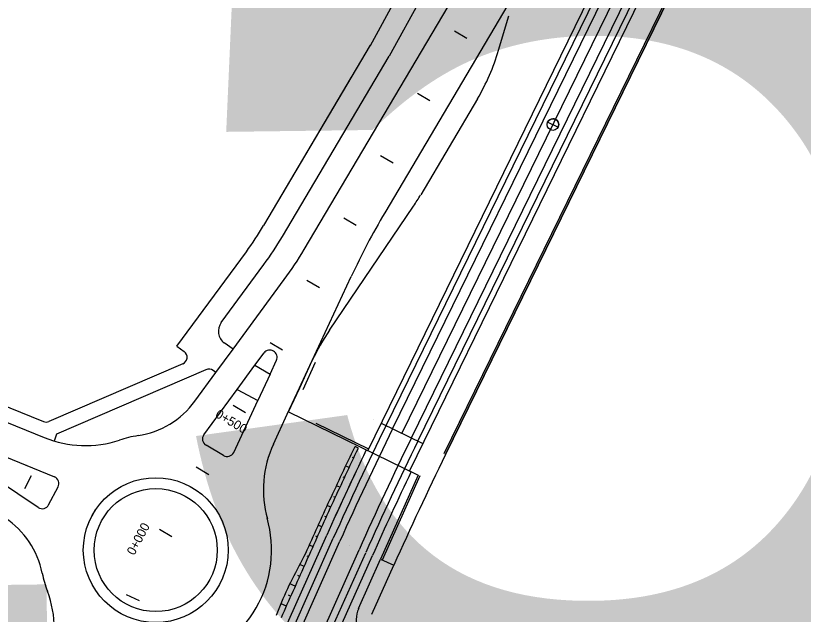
# Model space of a CAD drawing. Extents: x 6503541 to 6503743, y 5888004 to 5888145.
# Drawn here: x 6503689.662 to 6503692.272, y 5888095.259 to 5888097.244 of the extents above; entities that cross this region are included whole.
import ezdxf

# ---------------------------------------------------------------- set-up
doc = ezdxf.new("R2010")
doc.units = 0
doc.layers.add('12', color=7, linetype='Continuous')

msp = doc.modelspace()

# ---------------------------------------------------------------- linework, layer by layer
at = {"layer": '12'}
for p, q in [((6503691.4764, 5888098.3138), (6503690.8366, 5888097.1441)), ((6503691.1973, 5888097.6501), (6503690.8997, 5888097.1094)), ((6503691.6944, 5888097.5731), (6503690.8292, 5888095.8023)), ((6503690.8895, 5888095.8848), (6503691.7106, 5888097.5652)), ((6503690.9111, 5888095.8743), (6503691.7322, 5888097.5546)), ((6503690.9424, 5888095.859), (6503691.7634, 5888097.5394)), ((6503690.9736, 5888095.8437), (6503691.7947, 5888097.5241)), ((6503691.8324, 5888097.5056), (6503690.9672, 5888095.7348)), ((6503690.9952, 5888095.8332), (6503691.8163, 5888097.5135)), ((6503691.8999, 5888097.466), (6503691.0815, 5888095.791)), ((6503691.9079, 5888097.4688), (6503691.0868, 5888095.7884)), ((6503691.0868, 5888095.7884), (6503691.9079, 5888097.4688)), ((6503691.3672, 5888097.4049), (6503690.8855, 5888096.5904)), ((6503690.6183, 5888096.4687), (6503691.1416, 5888097.3535)), ((6503691.2627, 5888097.1291), (6503691.2968, 5888097.2437)), ((6503691.2627, 5888097.1291), (6503691.2968, 5888097.2437)), ((6503690.4841, 5888096.5481), (6503690.8377, 5888097.1461)), ((6503690.546, 5888096.5114), (6503690.8997, 5888097.1094)), ((6503690.4841, 5888096.5481), (6503690.7747, 5888097.0396)), ((6503691.1923, 5888096.9678), (6503691.0044, 5888096.6499)), ((6503691.1923, 5888096.9678), (6503691.0044, 5888096.6499)), ((6503690.7021, 5888096.2012), (6503690.9807, 5888096.6127)), ((6503690.7021, 5888096.2012), (6503690.9807, 5888096.6127)), ((6503690.1965, 5888096.1481), (6503690.4267, 5888096.4613)), ((6503690.3433, 5888096.2261), (6503690.4847, 5888096.4187)), ((6503690.6451, 5888096.1005), (6503690.7742, 5888096.3787)), ((6503690.3826, 5888096.1379), (6503690.5524, 5888096.3689)), ((6503690.1965, 5888096.1481), (6503690.2206, 5888096.1304)), ((6503690.3258, 5888096.0605), (6503690.3826, 5888096.1379)), ((6503690.4552, 5888096.0846), (6503690.4852, 5888096.1255)), ((6503690.2158, 5888096.089), (6503689.7725, 5888095.8983)), ((6503690.5052, 5888096.0555), (6503690.5263, 5888096.1012)), ((6503690.6037, 5888096.0098), (6503690.6451, 5888096.1005)), ((6503690.6089, 5888096.0225), (6503690.6451, 5888096.1005)), ((6503690.6147, 5888096.0048), (6503690.656, 5888096.0955)), ((6503690.2929, 5888096.07), (6503689.7971, 5888095.8567)), ((6503690.256, 5888095.9655), (6503690.3258, 5888096.0605)), ((6503690.3965, 5888096.0048), (6503690.4552, 5888096.0846)), ((6503690.4552, 5888096.0846), (6503690.5052, 5888096.0555)), ((6503690.5052, 5888096.0555), (6503690.4648, 5888095.9685)), ((6503689.4715, 5888096.0134), (6503689.7539, 5888095.8982)), ((6503690.5625, 5888095.9226), (6503690.6031, 5888096.0101)), ((6503690.5669, 5888095.9304), (6503690.6037, 5888096.0098)), ((6503690.6031, 5888096.0101), (6503690.6089, 5888096.0225)), ((6503690.6031, 5888096.0101), (6503690.6089, 5888096.0225)), ((6503690.286, 5888095.8543), (6503690.3965, 5888096.0048)), ((6503690.3965, 5888096.0048), (6503690.4648, 5888095.9685)), ((6503689.4533, 5888095.969), (6503689.7571, 5888095.845)), ((6503690.3847, 5888095.7959), (6503690.4648, 5888095.9685)), ((6503690.5669, 5888095.9304), (6503690.9964, 5888095.7206)), ((6503690.5165, 5888095.8234), (6503690.5625, 5888095.9226)), ((6503690.8475, 5888095.9054), (6503690.8475, 5888095.9054)), ((6503690.6566, 5888095.8933), (6503690.8318, 5888095.8077)), ((6503690.8734, 5888095.8927), (6503691.0114, 5888095.8253)), ((6503689.7971, 5888095.8567), (6503689.7902, 5888095.8334)), ((6503689.4791, 5888095.8418), (6503689.7906, 5888095.7147)), ((6503689.7369, 5888095.6133), (6503689.4568, 5888095.7996)), ((6503690.3507, 5888095.7854), (6503690.2931, 5888095.8195)), ((6503690.7981, 5888095.8104), (6503690.7871, 5888095.8156)), ((6503690.7771, 5888095.7805), (6503690.7827, 5888095.7779)), ((6503690.7673, 5888095.7453), (6503690.756, 5888095.7506)), ((6503690.9672, 5888095.7348), (6503690.9964, 5888095.7206)), ((6503690.7463, 5888095.7154), (6503690.752, 5888095.7127)), ((6503690.9964, 5888095.7206), (6503690.8716, 5888095.4414)), ((6503691.0019, 5888095.7181), (6503690.8771, 5888095.439)), ((6503689.7714, 5888095.6221), (6503689.8028, 5888095.6812)), ((6503690.7369, 5888095.6801), (6503690.7253, 5888095.6854)), ((6503690.7159, 5888095.6501), (6503690.7218, 5888095.6474)), ((6503690.7068, 5888095.6146), (6503690.695, 5888095.62)), ((6503690.686, 5888095.5846), (6503690.6919, 5888095.5819)), ((6503690.6771, 5888095.549), (6503690.6652, 5888095.5544)), ((6503689.741, 5888093.3912), (6503690.693, 5888095.5212)), ((6503690.6564, 5888095.5189), (6503690.6624, 5888095.5162)), ((6503688.2552, 5888090.0082), (6503690.7149, 5888095.5114)), ((6503688.2771, 5888089.9984), (6503690.7368, 5888095.5016)), ((6503690.6477, 5888095.4833), (6503690.6357, 5888095.4887)), ((6503688.3407, 5888089.97), (6503690.8004, 5888095.4732)), ((6503688.3626, 5888089.9602), (6503690.8223, 5888095.4634)), ((6503689.8183, 5888093.1583), (6503690.8442, 5888095.4537)), ((6503690.6268, 5888095.4532), (6503690.633, 5888095.4505)), ((6503690.7989, 5888095.2788), (6503690.8716, 5888095.4414)), ((6503690.8716, 5888095.4414), (6503690.9154, 5888095.4218)), ((6503690.6183, 5888095.4176), (6503690.6042, 5888095.4239)), ((6503690.8427, 5888095.2592), (6503690.9154, 5888095.4218)), ((6503690.5957, 5888095.3883), (6503690.6036, 5888095.3847)), ((6503690.5889, 5888095.3519), (6503690.5713, 5888095.3597)), ((6503690.5651, 5888095.3231), (6503690.5743, 5888095.319)), ((6503690.5596, 5888095.2861), (6503690.5417, 5888095.2941))]:
    msp.add_line(p, q, dxfattribs=at)
for points in [[(6503691.1574, 5888097.1681), (6503691.1161, 5888097.1925)], [(6503691.0353, 5888096.9615), (6503690.9939, 5888096.9859)], [(6503691.4254, 5888096.8913), (6503691.4599, 5888096.8745)], [(6503690.9131, 5888096.7549), (6503690.8718, 5888096.7794)], [(6503690.7909, 5888096.5483), (6503690.7496, 5888096.5728)], [(6503690.6688, 5888096.3418), (6503690.6274, 5888096.3662)], [(6503690.3826, 5888096.1379), (6503690.3537, 5888096.1589)], [(6503690.5466, 5888096.1352), (6503690.5053, 5888096.1596)], [(6503690.3258, 5888096.0605), (6503690.3166, 5888096.0672)], [(6503690.3831, 5888095.953), (6503690.4244, 5888095.9286)], [(6503690.5267, 5888095.2558), (6503690.5311, 5888095.267), (6503690.5354, 5888095.2782), (6503690.5398, 5888095.2894), (6503690.5442, 5888095.3005), (6503690.5491, 5888095.3115), (6503690.5539, 5888095.3225), (6503690.5588, 5888095.3334), (6503690.5637, 5888095.3444), (6503690.569, 5888095.3552), (6503690.5745, 5888095.3659), (6503690.58, 5888095.3766), (6503690.5854, 5888095.3873), (6503690.5909, 5888095.398), (6503690.5964, 5888095.4087), (6503690.6018, 5888095.4194), (6503690.6073, 5888095.4301), (6503690.6128, 5888095.4408), (6503690.6183, 5888095.4515), (6503690.6237, 5888095.4621), (6503690.6287, 5888095.4731), (6503690.6337, 5888095.484), (6503690.6386, 5888095.495), (6503690.6435, 5888095.5059), (6503690.6484, 5888095.5169), (6503690.6533, 5888095.5278), (6503690.6582, 5888095.5388), (6503690.6632, 5888095.5498), (6503690.6681, 5888095.5609), (6503690.6731, 5888095.5719), (6503690.6781, 5888095.583), (6503690.6831, 5888095.594), (6503690.6881, 5888095.6051), (6503690.6932, 5888095.6161), (6503690.6982, 5888095.6271), (6503690.7033, 5888095.6381), (6503690.7084, 5888095.6491), (6503690.7135, 5888095.6601), (6503690.7186, 5888095.6711), (6503690.7238, 5888095.6821), (6503690.7289, 5888095.6931), (6503690.734, 5888095.704), (6503690.7392, 5888095.715), (6503690.7444, 5888095.726), (6503690.7496, 5888095.7369), (6503690.7547, 5888095.7479), (6503690.7599, 5888095.7588), (6503690.7652, 5888095.7698), (6503690.7704, 5888095.7807), (6503690.7756, 5888095.7916), (6503690.7808, 5888095.8026), (6503690.7871, 5888095.8156)], [(6503690.5428, 5888095.2486), (6503690.5477, 5888095.2596), (6503690.5526, 5888095.2705), (6503690.5575, 5888095.2815), (6503690.5624, 5888095.2924), (6503690.5673, 5888095.3034), (6503690.5722, 5888095.3143), (6503690.5771, 5888095.3253), (6503690.582, 5888095.3362), (6503690.5869, 5888095.3472), (6503690.5918, 5888095.3582), (6503690.5966, 5888095.3691), (6503690.6015, 5888095.3801), (6503690.6064, 5888095.391), (6503690.6113, 5888095.402), (6503690.6162, 5888095.4129), (6503690.6211, 5888095.4239), (6503690.626, 5888095.4348), (6503690.6309, 5888095.4458), (6503690.6358, 5888095.4567), (6503690.6407, 5888095.4677), (6503690.6456, 5888095.4787), (6503690.6505, 5888095.4896), (6503690.6554, 5888095.5006), (6503690.6603, 5888095.5115), (6503690.6652, 5888095.5225), (6503690.6701, 5888095.5335), (6503690.6751, 5888095.5445), (6503690.68, 5888095.5556), (6503690.685, 5888095.5666), (6503690.69, 5888095.5776), (6503690.695, 5888095.5887), (6503690.7, 5888095.5997), (6503690.705, 5888095.6107), (6503690.71, 5888095.6217), (6503690.715, 5888095.6327), (6503690.7201, 5888095.6437), (6503690.7251, 5888095.6547), (6503690.7302, 5888095.6657), (6503690.7353, 5888095.6767), (6503690.7404, 5888095.6877), (6503690.7455, 5888095.6987), (6503690.7506, 5888095.7097), (6503690.7557, 5888095.7206), (6503690.7609, 5888095.7316), (6503690.766, 5888095.7426), (6503690.7712, 5888095.7535), (6503690.7763, 5888095.7645), (6503690.7815, 5888095.7754), (6503690.7867, 5888095.7864), (6503690.7919, 5888095.7973), (6503690.7981, 5888095.8104)], [(6503690.3022, 5888095.722), (6503690.2609, 5888095.7465)], [(6503689.7135, 5888095.7178), (6503689.691, 5888095.6754)], [(6503689.9256, 5888095.6055), (6503689.9031, 5888095.563)], [(6503690.1801, 5888095.5155), (6503690.1388, 5888095.5399)], [(6503690.0729, 5888095.3034), (6503690.0295, 5888095.324)]]:
    msp.add_lwpolyline(points, dxfattribs=at)
for centre, radius in [((6503691.4427, 5888096.8829), 0.0192), ((6503690.1264, 5888095.4719), 0.24), ((6503690.1264, 5888095.4719), 0.204)]:
    msp.add_circle(centre, radius, dxfattribs=at)
for centre, radius, start, end in [((6503690.5726, 5888097.3343), 0.72, 329.4002, 343.4364), ((6503690.5726, 5888097.3343), 0.72, 329.4002, 343.4364), ((6503691.4427, 5888096.8829), 0.0192, 29.5116, 153.9588), ((6503691.4427, 5888096.8829), 0.0192, 333.9588, 29.5116), ((6503690.3846, 5888097.0164), 0.72, 325.8891, 329.4002), ((6503690.3846, 5888097.0164), 0.72, 325.8891, 329.4), ((6503692.9513, 5888095.3687), 2.4, 149.4002, 155.1107), ((6503689.5854, 5888097.0795), 1.044, 323.6896, 329.4002), ((6503689.5854, 5888097.0795), 1.116, 323.6896, 329.4002), ((6503689.5854, 5888097.0795), 1.2, 323.6896, 329.4002), ((6503690.3819, 5888096.1977), 0.048, 143.6896, 233.9944), ((6503691.2982, 5888095.7974), 0.72, 145.8891, 155.1107), ((6503691.2982, 5888095.7974), 0.72, 145.8893, 155.1111), ((6503690.2063, 5888096.1111), 0.024, 293.2761, 53.6896), ((6503690.5046, 5888096.1113), 0.024, 335.1107, 143.6896), ((6503690.3024, 5888096.0479), 0.024, 53.6896, 113.2761), ((6503690.0239, 5888096.136), 0.288, 278.7795, 323.6896), ((6503689.763, 5888095.9204), 0.024, 247.7998, 293.2761), ((6503701.7241, 5888090.5908), 12.0588, 153.95881, 155.91738), ((6503690.1264, 5888095.4719), 0.384, 98.7775, 108.2797), ((6503690.3053, 5888095.8401), 0.024, 143.6896, 239.4002), ((6503701.7241, 5888090.5908), 12.0348, 153.95881, 155.91738), ((6503689.8931, 5888096.1784), 0.36, 247.7998, 288.2797), ((6503701.7241, 5888090.5908), 11.9652, 153.95881, 155.91738), ((6503701.7241, 5888090.5908), 11.9412, 153.95881, 155.91738), ((6503690.8431, 5888095.6719), 0.36, 155.1107, 195.5906), ((6503701.7241, 5888090.5908), 12.0828, 154.4362, 155.91738), ((6503701.7241, 5888090.5908), 12.0828, 154.45137, 155.91738), ((6503690.3629, 5888095.806), 0.024, 239.4002, 335.1107), ((6503701.7241, 5888090.5908), 11.8392, 153.95881, 155.91738), ((6503701.7241, 5888090.5908), 11.9172, 154.44221, 155.91738), ((6503701.7241, 5888090.5908), 11.9172, 154.44283, 155.91738), ((6503689.7816, 5888095.6925), 0.024, 332.0892, 67.7998), ((6503689.7502, 5888095.6333), 0.024, 236.3786, 332.0892), ((6503689.4679, 5888095.3383), 0.288, 11.4674, 56.3786), ((6503690.1264, 5888095.4719), 0.384, 283.9533, 16.1), ((6503690.1264, 5888095.4719), 0.384, 191.4674, 200.7656), ((6503689.4308, 5888095.2081), 0.36, 340.2857, 20.7656), ((6503690.8866, 5888095.2396), 0.096, 155.9174, 201.1797)]:
    msp.add_arc(centre, radius, start, end, dxfattribs=at)

# ---------------------------------------------------------------- texts
for s, height, rotation, p in [('15', 4.22297, 0.7393, (6503686.9056, 5888094.8628)), ('0+500', 0.03, 329.4002, (6503690.3211, 5888095.9146)), ('C', 0.0024, 63.9588, (6503690.9429, 5888095.8574)), ('0+000', 0.03, 62.0892, (6503690.0551, 5888095.4525)), ('C', 0.0024, 65.9174, (6503690.7692, 5888095.4858))]:
    msp.add_text(s, height=height, rotation=rotation, dxfattribs=at).set_placement(p)

doc.saveas('drawing.dxf')
